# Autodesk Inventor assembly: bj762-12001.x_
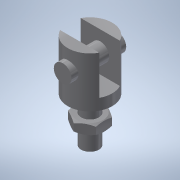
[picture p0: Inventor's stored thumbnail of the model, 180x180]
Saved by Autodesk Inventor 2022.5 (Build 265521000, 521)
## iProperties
Part Number: bj762-12001.x_
Material: 一般
Document SubType Name: Assembly
Designer: ImaoCorp
Sending System: SOLIDWORKS 2017-2017317
MC: AMD64
MC_MODEL: Intel64 Family 6 Model 60 Stepping 3, GenuineIntel
OS: Windows_NT
FRU: Parasolid Version 29.0, build 201,  4-17-2017
FORMAT: text
GUISE: transmit
KEY: bj762-12001
FILE: bj762-12001.x_t
DATE: Fri Mar 15 10:09:25 2019
Author: ImaoCorp
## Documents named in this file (3)
- X:\14_SW2022-Inv2022\00_全2023-1023新製品(TCC)まで\b\bj762-12001\BJ762-12001.iam
- X:\14_SW2022-Inv2022\00_全2023-1023新製品(TCC)まで\b\bj762-12001\bj762-12001_01.ipt
- X:\14_SW2022-Inv2022\00_全2023-1023新製品(TCC)まで\b\bj762-12001\bj762-12001_02.ipt
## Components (2 placed, 2 different names)
1. bj762-12001_01
2. bj762-12001_02
